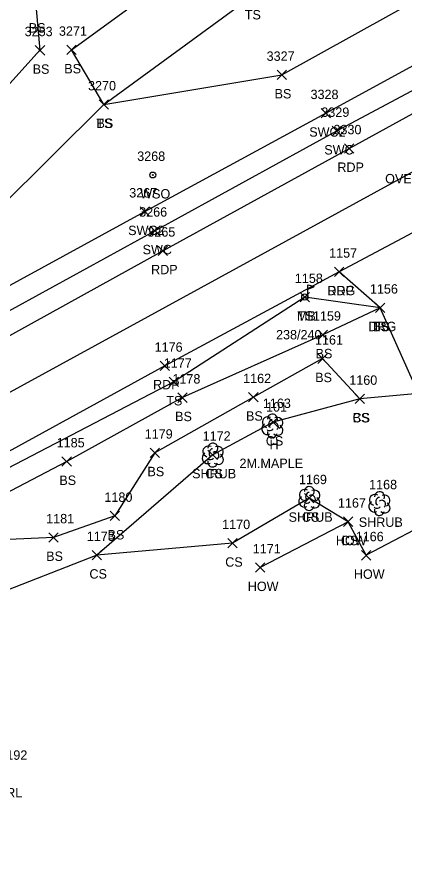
# Model space of a CAD drawing. Extents: x 1477930 to 1480780, y 774090 to 784647.
# Drawn here: x 1479682.6 to 1479765, y 774725.4 to 774907.7 of the extents above; entities that cross this region are included whole.
import ezdxf

# ---------------------------------------------------------------- set-up
doc = ezdxf.new("R2010")
doc.units = 0
for name, color, linetype in [('L_A', 7, 'Continuous'), ('L_C', 7, 'Continuous'), ('L_I', 7, 'Continuous'), ('L_TIC', 7, 'Continuous'), ('LBC', 7, 'Continuous'), ('LELB', 7, 'Continuous'), ('LMB', 7, 'Continuous'), ('LSH', 7, 'Continuous'), ('LTD', 7, 'Continuous'), ('P_A', 7, 'Continuous'), ('P_I', 7, 'Continuous'), ('P_TIC', 7, 'Continuous'), ('PET', 7, 'Continuous'), ('PRC', 7, 'Continuous'), ('R_A', 7, 'Continuous'), ('R_I', 7, 'Continuous'), ('R_TIC', 7, 'Continuous'), ('RDG', 7, 'Continuous'), ('RSW', 7, 'Continuous'), ('U_A', 7, 'Continuous'), ('U_I', 7, 'Continuous'), ('UWV', 7, 'Continuous')]:
    doc.layers.add(name, color=color, linetype=linetype)

msp = doc.modelspace()

# ---------------------------------------------------------------- linework, layer by layer
at = {"layer": 'L_TIC'}
for points in [[(1479686.43, 774899.61), (1479688.43, 774901.61)], [(1479688.43, 774899.61), (1479686.43, 774901.61)], [(1479693.16, 774899.7), (1479695.16, 774901.7)], [(1479695.16, 774899.7), (1479693.16, 774901.7)], [(1479737.89, 774894.37), (1479739.89, 774896.37)], [(1479739.89, 774894.37), (1479737.89, 774896.37)], [(1479700, 774888.08), (1479702, 774890.08)], [(1479702, 774888.08), (1479700, 774890.08)], [(1479700, 774888.08), (1479702, 774890.08)], [(1479702, 774888.08), (1479700, 774890.08)], [(1479700, 774888.08), (1479702, 774890.08)], [(1479702, 774888.08), (1479700, 774890.08)], [(1479742.76, 774847.1), (1479744.76, 774849.1)], [(1479744.76, 774847.1), (1479742.76, 774849.1)], [(1479758.78, 774844.84), (1479760.78, 774846.84)], [(1479760.78, 774844.84), (1479758.78, 774846.84)], [(1479758.78, 774844.84), (1479760.78, 774846.84)], [(1479760.78, 774844.84), (1479758.78, 774846.84)], [(1479746.61, 774839.08), (1479748.61, 774841.08)], [(1479748.61, 774839.08), (1479746.61, 774841.08)], [(1479746.52, 774834), (1479748.52, 774836)], [(1479748.52, 774834), (1479746.52, 774836)], [(1479714.88, 774829.05), (1479716.88, 774831.05)], [(1479716.88, 774829.05), (1479714.88, 774831.05)], [(1479731.81, 774825.8), (1479733.81, 774827.8)], [(1479733.81, 774825.8), (1479731.81, 774827.8)], [(1479716.72, 774825.7), (1479718.72, 774827.7)], [(1479718.72, 774825.7), (1479716.72, 774827.7)], [(1479754.47, 774825.43), (1479756.47, 774827.43)], [(1479756.47, 774825.43), (1479754.47, 774827.43)], [(1479754.47, 774825.43), (1479756.47, 774827.43)], [(1479756.47, 774825.43), (1479754.47, 774827.43)], [(1479736.02, 774820.5), (1479738.02, 774822.5)], [(1479738.02, 774820.5), (1479736.02, 774822.5)], [(1479710.85, 774813.98), (1479712.85, 774815.98)], [(1479712.85, 774813.98), (1479710.85, 774815.98)], [(1479723.16, 774813.54), (1479725.16, 774815.54)], [(1479725.16, 774813.54), (1479723.16, 774815.54)], [(1479692.11, 774812.12), (1479694.11, 774814.12)], [(1479694.11, 774812.12), (1479692.11, 774814.12)], [(1479743.68, 774804.29), (1479745.68, 774806.29)], [(1479745.68, 774804.29), (1479743.68, 774806.29)], [(1479702.35, 774800.53), (1479704.35, 774802.53)], [(1479704.35, 774800.53), (1479702.35, 774802.53)], [(1479751.98, 774799.31), (1479753.98, 774801.31)], [(1479753.98, 774799.31), (1479751.98, 774801.31)], [(1479751.98, 774799.31), (1479753.98, 774801.31)], [(1479753.98, 774799.31), (1479751.98, 774801.31)], [(1479689.31, 774795.96), (1479691.31, 774797.96)], [(1479691.31, 774795.96), (1479689.31, 774797.96)], [(1479727.39, 774794.73), (1479729.39, 774796.73)], [(1479729.39, 774794.73), (1479727.39, 774796.73)], [(1479698.51, 774792.2), (1479700.51, 774794.2)], [(1479700.51, 774792.2), (1479698.51, 774794.2)], [(1479698.51, 774792.2), (1479700.51, 774794.2)], [(1479700.51, 774792.2), (1479698.51, 774794.2)], [(1479755.8, 774792.15), (1479757.8, 774794.15)], [(1479757.8, 774792.15), (1479755.8, 774794.15)], [(1479733.24, 774789.55), (1479735.24, 774791.55)], [(1479735.24, 774789.55), (1479733.24, 774791.55)]]:
    msp.add_lwpolyline(points, dxfattribs=at)
at = {"layer": 'LBC'}
msp.add_lwpolyline([(1479775.93, 774796.14), (1479772.75, 774801.56), (1479756.8, 774793.15), (1479752.98, 774800.31), (1479734.24, 774790.55)], dxfattribs=at)
at = {"layer": 'LELB'}
for points in [[(1479657.71, 774852.79), (1479678.77, 774867.01), (1479701, 774889.08), (1479732.59, 774912.18), (1479741.3, 774922.23), (1479718.58, 774955.17), (1479686.39, 774981.9), (1479667.59, 775015.02), (1479668.33, 775036.3)], [(1479580.44, 774995.69), (1479587.48, 775002.68), (1479612.24, 774984.69), (1479628.11, 774970.45), (1479636.94, 774956.73), (1479624.94, 774926.71), (1479649.32, 774906.86), (1479653.38, 774932.32), (1479686.61, 774909.39), (1479687.43, 774900.61), (1479665.73, 774876.56), (1479654.12, 774867.16), (1479644.81, 774869.01), (1479633.41, 774850.84), (1479636.06, 774836.76), (1479657.71, 774852.79)], [(1479701, 774889.08), (1479694.16, 774900.7), (1479723.17, 774921.93), (1479710.14, 774943.37), (1479698.67, 774953.6), (1479671.51, 774967.57)], [(1479701, 774889.08), (1479738.89, 774895.37), (1479785.03, 774921.09), (1479816.51, 774941.39), (1479839.92, 774951.74)], [(1479759.78, 774845.84), (1479743.76, 774848.1), (1479715.88, 774830.05), (1479665.38, 774803.72), (1479650.39, 774795.36), (1479602.85, 774770.48), (1479561.12, 774746.99), (1479522.68, 774719.79), (1479509.66, 774713.24), (1479482.17, 774702.33), (1479465.55, 774693.3), (1479450.04, 774680.68), (1479444.99, 774662.35), (1479439.28, 774645.05), (1479436.33, 774630.12), (1479434.69, 774607.73), (1479420.75, 774561.37), (1479408.24, 774515.83), (1479404.08, 774492.53), (1479401.08, 774483.2), (1479386.93, 774431.62)], [(1479759.78, 774845.84), (1479747.61, 774840.08), (1479717.72, 774826.7), (1479693.11, 774813.12), (1479667.75, 774799.87), (1479652.34, 774792.25), (1479604.7, 774766.29), (1479564.8, 774741.45), (1479523.94, 774717.4), (1479484.23, 774697.29), (1479467.35, 774689.75), (1479454.86, 774676.9), (1479444.99, 774662.35), (1479436.47, 774645.61)], [(1479755.47, 774826.43), (1479747.52, 774835), (1479732.81, 774826.8), (1479711.85, 774814.98), (1479703.35, 774801.53), (1479690.31, 774796.96), (1479675.98, 774796.31), (1479667.39, 774786.04), (1479656.48, 774787.57), (1479654.62, 774789.12), (1479607, 774760.65), (1479567.24, 774738.02), (1479525.29, 774711.93), (1479486.59, 774691.55), (1479469.23, 774685.68), (1479454.86, 774676.9)], [(1479767.9, 774827.58), (1479755.47, 774826.43), (1479737.02, 774821.5), (1479724.16, 774814.54), (1479699.51, 774793.2), (1479676.96, 774784.41), (1479668.59, 774775.62)], [(1479752.98, 774800.31), (1479744.68, 774805.29), (1479728.39, 774795.73), (1479699.51, 774793.2)]]:
    msp.add_lwpolyline(points, dxfattribs=at)
at = {"layer": 'LMB'}
for p, q in [((1479744.41, 774850.7), (1479745.71, 774850.32)), ((1479744.42, 774848.11), (1479744.42, 774850.7)), ((1479744.42, 774849.8), (1479745.7, 774850.31)), ((1479743.76, 774848.1), (1479743.76, 774848.1))]:
    msp.add_line(p, q, dxfattribs=at)
msp.add_circle((1479743.76, 774848.1), 0.656, dxfattribs=at)
at = {"layer": 'LSH'}
for p, q in [((1479724.16, 774814.54), (1479724.16, 774814.54)), ((1479724.16, 774814.54), (1479724.16, 774814.54)), ((1479744.68, 774805.29), (1479744.68, 774805.29)), ((1479744.68, 774805.29), (1479744.68, 774805.29)), ((1479759.6, 774804.21), (1479759.6, 774804.21)), ((1479759.6, 774804.21), (1479759.6, 774804.21))]:
    msp.add_line(p, q, dxfattribs=at)
for centre in [(1479724.21, 774815.98), (1479744.73, 774806.73), (1479759.65, 774805.64)]:
    msp.add_arc(centre, 1.05, 335.5272, 180.9563, dxfattribs=at)
for centre, major_axis, ratio, start_param, end_param in [((1479723.37, 774815.21), (1.21, -0.51), 0.895232, 1.570796, 4.712389), ((1479723.95, 774815), (-0.208, -0.792), 0.645439, 3.141593, 6.283185), ((1479724.66, 774814.38), (-0.5, 0.667), 0.989748, 3.141593, 6.283185), ((1479725.2, 774815.13), (-1.14, -0.48), 0.949671, 1.570796, 4.712389), ((1479723.08, 774813.83), (0.58, -1.04), 0.959034, 3.141593, 6.283185), ((1479724.16, 774813.04), (0.26, 1.06), 0.942809, 1.570796, 4.712389), ((1479723.7, 774813.79), (-0.625, -0.083), 0.423636, 0, 3.141593), ((1479725.16, 774813.71), (-1.09, 0.79), 0.841452, 1.570796, 4.712389), ((1479743.89, 774805.96), (1.21, -0.51), 0.895232, 1.570796, 4.712389), ((1479744.47, 774805.75), (-0.208, -0.792), 0.645439, 3.141593, 6.283185), ((1479745.18, 774805.12), (-0.5, 0.667), 0.989748, 3.141593, 6.283185), ((1479745.72, 774805.87), (-1.14, -0.48), 0.949671, 1.570796, 4.712389), ((1479758.81, 774804.88), (1.21, -0.51), 0.895232, 1.570796, 4.712389), ((1479760.65, 774804.79), (-1.14, -0.48), 0.949671, 1.570796, 4.712389), ((1479743.6, 774804.58), (0.58, -1.04), 0.959034, 3.141593, 6.283185), ((1479744.68, 774803.79), (0.26, 1.06), 0.942809, 1.570796, 4.712389), ((1479744.22, 774804.54), (-0.625, -0.083), 0.423636, 0, 3.141593), ((1479745.68, 774804.46), (-1.09, 0.79), 0.841452, 1.570796, 4.712389), ((1479758.52, 774803.5), (0.58, -1.04), 0.959034, 3.141593, 6.283185), ((1479759.4, 774804.67), (-0.208, -0.792), 0.645439, 3.141593, 6.283185), ((1479760.1, 774804.04), (-0.5, 0.667), 0.989748, 3.141593, 6.283185), ((1479760.6, 774803.38), (-1.09, 0.79), 0.841452, 1.570796, 4.712389), ((1479759.6, 774802.71), (0.26, 1.06), 0.942809, 1.570796, 4.712389), ((1479759.15, 774803.46), (-0.625, -0.083), 0.423636, 0, 3.141593)]:
    msp.add_ellipse(centre, major_axis=major_axis, ratio=ratio, start_param=start_param, end_param=end_param, dxfattribs=at)
at = {"layer": 'LTD'}
msp.add_line((1479736.82, 774820.73), (1479736.82, 774820.73), dxfattribs=at)
msp.add_line((1479736.82, 774820.73), (1479736.82, 774820.73), dxfattribs=at)
msp.add_arc((1479736.87, 774822.16), 1.05, 335.5272, 180.9563, dxfattribs=at)
for centre, major_axis, ratio, start_param, end_param in [((1479736.03, 774821.4), (1.21, -0.51), 0.895232, 1.570796, 4.712389), ((1479737.86, 774821.31), (-1.14, -0.48), 0.949671, 1.570796, 4.712389), ((1479735.74, 774820.02), (0.58, -1.04), 0.959034, 3.141593, 6.283185), ((1479736.61, 774821.19), (-0.208, -0.792), 0.645439, 3.141593, 6.283185), ((1479737.32, 774820.56), (-0.5, 0.667), 0.989748, 3.141593, 6.283185), ((1479737.82, 774819.9), (-1.09, 0.79), 0.841452, 1.570796, 4.712389), ((1479736.82, 774819.23), (0.26, 1.06), 0.942809, 1.570796, 4.712389), ((1479736.36, 774819.98), (-0.625, -0.083), 0.423636, 0, 3.141593)]:
    msp.add_ellipse(centre, major_axis=major_axis, ratio=ratio, start_param=start_param, end_param=end_param, dxfattribs=at)
at = {"layer": 'P_TIC'}
for points in [[(1479752.19, 774878.74), (1479754.19, 774880.74)], [(1479754.19, 774878.74), (1479752.19, 774880.74)], [(1479712.57, 774856.96), (1479714.57, 774858.96)], [(1479714.57, 774856.96), (1479712.57, 774858.96)], [(1479750.05, 774852.49), (1479752.05, 774854.49)], [(1479752.05, 774852.49), (1479750.05, 774854.49)], [(1479712.99, 774832.47), (1479714.99, 774834.47)], [(1479714.99, 774832.47), (1479712.99, 774834.47)]]:
    msp.add_lwpolyline(points, dxfattribs=at)
at = {"layer": 'PET'}
for points in [[(1479458.85, 774725.87), (1479463.75, 774725.49), (1479503.78, 774746.04), (1479529.26, 774759.88), (1479547.26, 774769.69), (1479593.15, 774794.19), (1479638.49, 774817.33), (1479672.22, 774835.12), (1479713.57, 774857.96), (1479753.19, 774879.74), (1479794.61, 774902.46), (1479830.33, 774920.88), (1479861.74, 774937.83), (1479877.76, 774946.85), (1479905.13, 774960.92), (1479936.65, 774977.61), (1479958.81, 774989.4), (1479973, 774995.93), (1480008.35, 775014.95)], [(1480020.8, 774996.12), (1479976.43, 774973.17), (1479932.79, 774950.42), (1479923.24, 774944.9), (1479898.9, 774932.87), (1479865.62, 774915.8), (1479836.8, 774900.06), (1479810.76, 774886.26), (1479791.96, 774875.61), (1479773.29, 774865.35), (1479751.05, 774853.49), (1479713.99, 774833.47), (1479663.95, 774806)]]:
    msp.add_lwpolyline(points, dxfattribs=at)
at = {"layer": 'PRC'}
msp.add_lwpolyline([(1480015.89, 775005.87), (1479971.79, 774982.46), (1479929.14, 774959.03), (1479892.61, 774942.34), (1479860.44, 774925.31), (1479806.49, 774896.54), (1479658.45, 774815.54), (1479643.75, 774807.57), (1479597.62, 774782.97), (1479555.61, 774761.16), (1479513.42, 774740.32), (1479471, 774718.6), (1479432.73, 774701.1), (1479418.32, 774694.97), (1479344.83, 774660.92), (1479298.6, 774640.39), (1479262.12, 774624.4), (1479219.63, 774609.01), (1479186.74, 774593.83)], dxfattribs=at)
at = {"layer": 'R_TIC'}
for points in [[(1479747.23, 774886.23), (1479749.23, 774888.23)], [(1479749.23, 774886.23), (1479747.23, 774888.23)], [(1479749.54, 774882.44), (1479751.54, 774884.44)], [(1479751.54, 774882.44), (1479749.54, 774884.44)], [(1479708.72, 774865.29), (1479710.72, 774867.29)], [(1479710.72, 774865.29), (1479708.72, 774867.29)], [(1479710.89, 774861.21), (1479712.89, 774863.21)], [(1479712.89, 774861.21), (1479710.89, 774863.21)], [(1479750.05, 774852.49), (1479752.05, 774854.49)], [(1479752.05, 774852.49), (1479750.05, 774854.49)], [(1479758.78, 774844.84), (1479760.78, 774846.84)], [(1479760.78, 774844.84), (1479758.78, 774846.84)], [(1479758.78, 774844.84), (1479760.78, 774846.84)], [(1479760.78, 774844.84), (1479758.78, 774846.84)]]:
    msp.add_lwpolyline(points, dxfattribs=at)
at = {"layer": 'RDG'}
for points in [[(1479759.78, 774845.84), (1479751.05, 774853.49)], [(1479784.33, 774796.2), (1479767.9, 774827.58), (1479759.78, 774845.84)]]:
    msp.add_lwpolyline(points, dxfattribs=at)
at = {"layer": 'RSW'}
for points in [[(1479454.05, 774732.2), (1479457.36, 774735.51), (1479461.55, 774734.41), (1479499.97, 774753.7), (1479531.62, 774770.46), (1479545.78, 774777.94), (1479596.7, 774804.86), (1479626.34, 774821.05), (1479665.84, 774842.34), (1479709.72, 774866.29), (1479748.23, 774887.23), (1479790.98, 774910.55), (1479825.88, 774929.42), (1479857.89, 774946.35), (1479880.81, 774958.36), (1479898.02, 774967.81), (1479932.31, 774985.56), (1479966.42, 775003.67), (1480005.03, 775023.74)], [(1479458.85, 774725.87), (1479459.6, 774730), (1479502.04, 774749.23), (1479530.65, 774764.31), (1479546.64, 774772.58), (1479592.5, 774796.78), (1479632.83, 774818.63), (1479668.4, 774838.36), (1479711.89, 774862.21), (1479750.54, 774883.44), (1479792.95, 774906.12), (1479828.15, 774924.96), (1479859.81, 774941.82), (1479882.29, 774953.43), (1479899.45, 774962.93), (1479935.39, 774981.77), (1479958.84, 774993.68), (1479967.68, 774998.52), (1480006.53, 775018.83)]]:
    msp.add_lwpolyline(points, dxfattribs=at)
at = {"layer": 'UWV'}
for radius in [0.625, 0.0833]:
    msp.add_circle((1479711.42, 774874.08), radius, dxfattribs=at)

# ---------------------------------------------------------------- texts
at = {"layer": 'L_A'}
for s, p in [('TS', (1479731, 774907.18)), ('BS', (1479685.05, 774904.39)), ('BS', (1479685.87, 774895.61)), ('BS', (1479692.6, 774895.7)), ('BS', (1479737.33, 774890.37)), ('TS', (1479699.41, 774884.08)), ('BS', (1479699.44, 774884.08)), ('BS', (1479699.44, 774884.08)), ('TS', (1479742.17, 774843.1)), ('MB', (1479742.07, 774843.1)), ('TS', (1479758.19, 774840.84)), ('BS', (1479758.22, 774840.84)), ('BS', (1479746.05, 774835.08)), ('BS', (1479745.96, 774830)), ('TS', (1479714.29, 774825.05)), ('BS', (1479716.17, 774821.7)), ('BS', (1479731.25, 774821.8)), ('CS', (1479753.91, 774821.43)), ('BS', (1479753.91, 774821.43)), ('CS', (1479735.46, 774816.5)), ('H', (1479736.25, 774815.73)), ('BS', (1479710.29, 774809.98)), ('SHRUB', (1479719.79, 774809.54)), ('CS', (1479722.6, 774809.54)), ('BS', (1479691.55, 774808.12)), ('SHRUB', (1479740.31, 774800.29)), ('CS', (1479743.12, 774800.29)), ('SHRUB', (1479755.23, 774799.21)), ('BS', (1479701.8, 774796.53)), ('HOW', (1479750.36, 774795.31)), ('CS', (1479751.42, 774795.31)), ('BS', (1479688.75, 774791.96)), ('CS', (1479726.83, 774790.73)), ('CS', (1479697.95, 774788.2)), ('CS', (1479697.95, 774788.2)), ('HOW', (1479754.19, 774788.15)), ('HOW', (1479731.63, 774785.55)), ('BRL', (1479678.46, 774741.65))]:
    msp.add_text(s, height=2, dxfattribs=at).set_placement(p)
at = {"layer": 'L_C'}
for s, p in [('238/240', (1479737.64, 774839.1)), ('2M.MAPLE', (1479729.86, 774811.73))]:
    msp.add_text(s, height=2, dxfattribs=at).set_placement(p)
at = {"layer": 'L_I'}
for s, p in [('3253', (1479684.17, 774903.61)), ('3271', (1479691.46, 774903.7)), ('3327', (1479735.63, 774898.37)), ('3270', (1479697.65, 774892.08)), ('3270', (1479697.65, 774892.08)), ('3270', (1479697.65, 774892.08)), ('1158', (1479741.64, 774851.1)), ('1158', (1479741.64, 774851.1)), ('1156', (1479757.6, 774848.84)), ('1156', (1479757.6, 774848.84)), ('1159', (1479745.48, 774843.08)), ('1161', (1479745.92, 774838)), ('1177', (1479713.76, 774833.05)), ('1178', (1479715.6, 774829.7)), ('1162', (1479730.64, 774829.8)), ('1160', (1479753.21, 774829.43)), ('1160', (1479753.21, 774829.43)), ('1163', (1479734.84, 774824.5)), ('101', (1479735.51, 774823.73)), ('1179', (1479709.71, 774817.98)), ('1172', (1479722.03, 774817.54)), ('1172', (1479722.03, 774817.54)), ('1185', (1479690.98, 774816.12)), ('1169', (1479742.5, 774808.29)), ('1169', (1479742.5, 774808.29)), ('1168', (1479757.43, 774807.21)), ('1180', (1479701.14, 774804.53)), ('1167', (1479750.8, 774803.31)), ('1167', (1479750.8, 774803.31)), ('1181', (1479688.75, 774799.96)), ('1170', (1479726.18, 774798.73)), ('1173', (1479697.39, 774796.2)), ('1173', (1479697.39, 774796.2)), ('1166', (1479754.58, 774796.15)), ('1171', (1479732.69, 774793.55)), ('1192', (1479678.79, 774749.65))]:
    msp.add_text(s, height=2, dxfattribs=at).set_placement(p)
at = {"layer": 'P_A'}
for p in [(1479750.68, 774874.74), (1479711.06, 774852.96), (1479748.54, 774848.49), (1479711.48, 774828.47)]:
    msp.add_text('RDP', height=2, dxfattribs=at).set_placement(p)
at = {"layer": 'P_I'}
for s, p in [('3330', (1479749.85, 774882.74)), ('3265', (1479710.26, 774860.96)), ('1157', (1479748.93, 774856.49)), ('1176', (1479711.81, 774836.47))]:
    msp.add_text(s, height=2, dxfattribs=at).set_placement(p)
at = {"layer": 'R_A'}
for s, p in [('SWC2', (1479744.7, 774882.23)), ('SWC', (1479747.9, 774878.44)), ('SWC2', (1479706.19, 774861.29)), ('SWC', (1479709.26, 774857.21)), ('DRG', (1479748.54, 774848.49)), ('DRG', (1479757.27, 774840.84)), ('DRG', (1479757.27, 774840.84))]:
    msp.add_text(s, height=2, dxfattribs=at).set_placement(p)
at = {"layer": 'R_I'}
for s, p in [('3328', (1479744.97, 774890.23)), ('3329', (1479747.27, 774886.44)), ('3267', (1479706.41, 774869.29)), ('3266', (1479708.53, 774865.21)), ('1157', (1479748.93, 774856.49)), ('1156', (1479757.6, 774848.84)), ('1156', (1479757.6, 774848.84))]:
    msp.add_text(s, height=2, dxfattribs=at).set_placement(p)
at = {"layer": 'U_A'}
for s, p in [('OVERHEAD', (1479760.84, 774872.3)), ('WSO', (1479708.75, 774869.08))]:
    msp.add_text(s, height=2, dxfattribs=at).set_placement(p)
at = {"layer": 'U_I'}
msp.add_text('3268', height=2, dxfattribs=at).set_placement((1479708.11, 774877.08))

doc.saveas('drawing.dxf')
